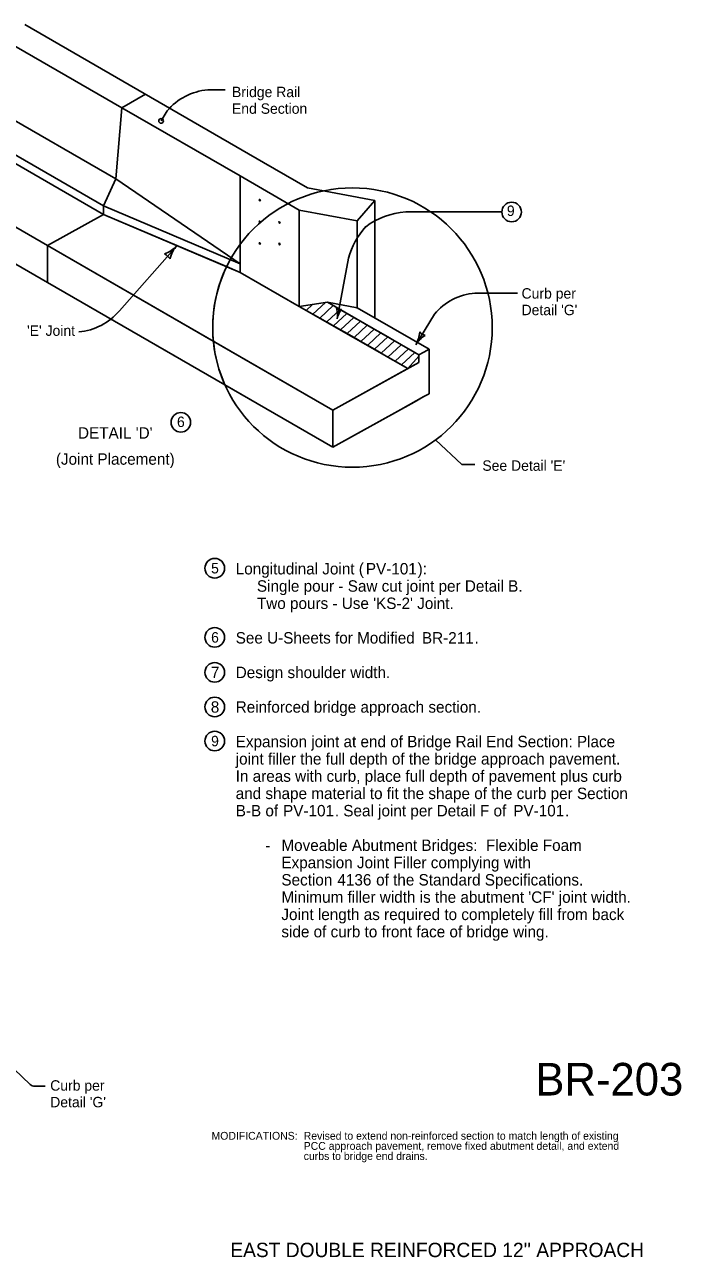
# Model space of a CAD drawing. Extents: x 9234 to 81668, y 5635 to 15999.
# Drawn here: x 19394 to 20400, y 12314 to 14204 of the extents above; entities that cross this region are included whole.
import ezdxf

# ---------------------------------------------------------------- set-up
doc = ezdxf.new("R2010")
doc.units = 0
for name, color, linetype in [('Alignment', 7, 'Continuous'), ('PC_REBAR', 7, 'Continuous'), ('PS_BOLT', 7, 'Continuous'), ('PS_CONST', 7, 'Continuous'), ('PS_DIM', 7, 'Continuous'), ('SheetAddenda', 7, 'Continuous'), ('SurEdgeShoulderUnpaved', 7, 'Continuous')]:
    doc.layers.add(name, color=color, linetype=linetype)

msp = doc.modelspace()

# ---------------------------------------------------------------- linework, layer by layer
at = {"layer": 'PC_REBAR'}
msp.add_circle((19602.7, 14056.8), 3.54, dxfattribs=at)
at = {"layer": 'PS_CONST'}
for centre, radius, start, end in [((19956.7, 13735.5), 42.5, 328.7108, 356.7833), ((20029.3, 13691.4), 42.5, 120.6383, 148.7108), ((20011.5, 13743.9), 16.4, 220.9775, 256.4442)]:
    msp.add_arc(centre, radius, start, end, dxfattribs=at)
at = {"layer": 'PS_DIM'}
for p, q in [((19393.7, 14204.4), (19759.7, 13993.1)), ((19542.8, 14076.9), (19357.8, 14183.7)), ((19674.2, 14104.5), (19701.1, 14104.5)), ((19533.4, 13967.8), (19348.4, 14074.6)), ((19723.8, 13972.4), (19542.8, 14076.9)), ((19602.7, 14056.8), (19612, 14072.1)), ((19514.5, 13926.4), (19329.5, 14033.2)), ((19759.7, 13993.1), (19827, 13954.2)), ((19723.8, 13972.4), (19723.8, 13824.5)), ((19814.4, 13920.1), (19723.8, 13972.4)), ((19827, 13954.2), (19930.2, 13934.9)), ((19930.2, 13934.9), (19930.2, 13754.8)), ((19514.5, 13913.3), (19428.7, 13865.7)), ((19514.5, 13913.3), (19428.7, 13865.7)), ((19703.2, 13833.3), (19514.5, 13913.3)), ((19723.8, 13824.5), (19514.5, 13913.3)), ((19814.4, 13920.1), (19814.4, 13772.2)), ((19814.4, 13920.1), (19903.3, 13903.5)), ((19977.6, 13917.5), (20125.1, 13917.5)), ((19903.3, 13770.3), (19903.3, 13903.5)), ((19428.7, 13865.7), (19428.7, 13809.1)), ((19682.8, 13719), (19428.7, 13865.7)), ((19428.7, 13865.7), (19428.7, 13809.1)), ((19428.7, 13865.7), (19682.8, 13719)), ((19428.7, 13865.7), (19865.9, 13613.3)), ((19627.2, 13866), (19538.8, 13765.7)), ((19889.8, 13846.3), (19872.6, 13753.3)), ((19723.8, 13824.5), (19703.2, 13833.3)), ((19814.4, 13772.2), (19723.8, 13824.5)), ((19814.4, 13772.2), (19723.8, 13824.5)), ((19428.7, 13809.1), (19865.9, 13556.7)), ((19428.7, 13809.1), (19700.6, 13652.1)), ((20083.8, 13792.9), (20149, 13792.9)), ((19857.7, 13778.9), (19814.4, 13772.2)), ((19857.7, 13778.9), (19814.4, 13772.2)), ((19877.6, 13736.6), (19814.4, 13772.2)), ((19814.4, 13772.2), (19814.4, 13772.2)), ((19814.4, 13772.2), (19877.6, 13736.6)), ((19977.3, 13679.1), (19814.4, 13772.2)), ((19980.9, 13677), (19814.4, 13772.2)), ((19814.4, 13772.2), (19814.4, 13772.2)), ((19834.7, 13775.3), (19824.9, 13766.3)), ((19854.9, 13778.4), (19835.5, 13760.4)), ((19866.7, 13773.7), (19846, 13754.5)), ((19877.1, 13767.6), (19856.6, 13748.6)), ((19898, 13755.6), (19857.7, 13778.9)), ((19903.3, 13770.3), (19857.7, 13778.9)), ((19857.7, 13778.9), (19898, 13755.6)), ((19997.8, 13698), (19857.7, 13778.9)), ((19857.7, 13778.9), (19903.3, 13770.3)), ((19887.6, 13761.6), (19867.2, 13742.7)), ((20013.5, 13706.7), (19903.3, 13770.3)), ((20013.5, 13706.7), (19903.3, 13770.3)), ((19993, 13713.5), (20021.6, 13760.5)), ((19877.6, 13736.6), (19898, 13755.6)), ((19898, 13755.6), (19877.6, 13736.6)), ((19898, 13755.6), (19877.6, 13736.6)), ((19888, 13730.6), (19908.4, 13749.6)), ((19908.4, 13749.6), (19888, 13730.6)), ((19908.4, 13749.6), (19888, 13730.6)), ((19908.4, 13749.6), (19898, 13755.6)), ((19898, 13755.6), (19908.4, 13749.6)), ((19898.4, 13724.6), (19918.8, 13743.6)), ((19918.8, 13743.6), (19898.4, 13724.6)), ((19918.8, 13743.6), (19898.4, 13724.6)), ((19918.8, 13743.6), (19908.4, 13749.6)), ((19908.4, 13749.6), (19918.8, 13743.6)), ((19929.2, 13737.6), (19918.8, 13743.6)), ((19918.8, 13743.6), (19929.2, 13737.6)), ((19877.6, 13736.6), (19888, 13730.6)), ((19888, 13730.6), (19898.4, 13724.6)), ((19898.4, 13724.6), (19908.8, 13718.6)), ((19908.8, 13718.6), (19929.2, 13737.6)), ((19929.2, 13737.6), (19908.8, 13718.6)), ((19929.2, 13737.6), (19908.8, 13718.6)), ((19939.5, 13731.6), (19919.4, 13713)), ((19929.6, 13706.6), (19950, 13725.6)), ((19950, 13725.6), (19929.6, 13706.6)), ((19950, 13725.6), (19929.6, 13706.6)), ((19960.4, 13719.6), (19950, 13725.6)), ((19950, 13725.6), (19960.4, 13719.6)), ((19682.8, 13719), (19865.9, 13613.3)), ((19865.9, 13613.3), (19682.8, 13719)), ((19908.8, 13718.6), (19929.6, 13706.6)), ((19929.6, 13706.6), (19940, 13700.6)), ((19940, 13700.6), (19960.4, 13719.6)), ((19960.4, 13719.6), (19940, 13700.6)), ((19960.4, 13719.6), (19940, 13700.6)), ((19970.9, 13713.5), (19950.5, 13694.5)), ((19981.9, 13707.2), (19961.5, 13688.2)), ((20013.5, 13706.7), (20005.6, 13702.3)), ((20005.6, 13702.3), (20013.5, 13706.7)), ((20013.5, 13706.7), (20005.6, 13702.3)), ((20013.5, 13638.4), (20013.5, 13706.7)), ((19865.9, 13613.3), (19997.8, 13686.3)), ((19940, 13700.6), (19950.5, 13694.5)), ((19950.5, 13694.5), (19971.2, 13682.6)), ((19971.2, 13682.6), (19991.6, 13701.5)), ((19991.6, 13701.5), (19971.2, 13682.6)), ((19991.6, 13701.5), (19971.2, 13682.6)), ((19980.9, 13677), (19997.8, 13696.1)), ((19997.8, 13696.1), (19980.9, 13677)), ((19980.9, 13677), (19997.8, 13696.1)), ((19997.8, 13686.3), (19980.9, 13677)), ((19980.9, 13677), (19997.8, 13686.3)), ((19997.8, 13698), (19991.6, 13701.5)), ((19991.6, 13701.5), (19997.8, 13698)), ((20005.6, 13702.3), (19997.8, 13698)), ((19997.8, 13698), (20005.6, 13702.3)), ((20005.6, 13702.3), (19997.8, 13698)), ((19997.8, 13696.1), (19997.8, 13698)), ((19997.8, 13686.3), (19997.8, 13698)), ((19997.8, 13686.3), (19997.8, 13696.1)), ((19865.9, 13613.3), (19980.9, 13677)), ((19980.9, 13677), (19865.9, 13613.3)), ((19971.2, 13682.6), (19977.3, 13679.1)), ((19980.9, 13677), (19977.3, 13679.1)), ((19977.3, 13679.1), (19980.9, 13677)), ((19700.6, 13652.1), (19865.9, 13556.7)), ((19970.4, 13614.5), (20005.6, 13634.1)), ((19990.5, 13625.7), (20005.6, 13634.1)), ((20005.6, 13634.1), (20013.5, 13638.4)), ((20013.5, 13638.4), (20005.6, 13634.1)), ((19865.9, 13556.7), (19990.5, 13625.7)), ((19865.9, 13556.7), (19865.9, 13613.3)), ((20023.4, 13567.7), (20063.8, 13529.7)), ((20063.8, 13529.7), (20083.6, 13529.7)), ((19365.1, 12614.3), (19402.3, 12579.4)), ((19409.1, 12576.7), (19425, 12576.7))]:
    msp.add_line(p, q, dxfattribs=at)
for points in [[(19542.8, 14076.9), (19578.6, 14097.6)], [(19514.5, 13913.3), (19514.5, 13926.4), (19533.4, 13967.8), (19542.8, 14076.9)], [(19514.5, 13913.3), (19329.5, 14020.1)], [(19243.7, 13972.5), (19428.7, 13865.7)], [(19514.5, 13926.4), (19723.8, 13837.6), (19533.4, 13967.8)], [(19903.3, 13903.5), (19930.2, 13934.9)], [(19428.7, 13809.1), (19243.7, 13915.9)], [(19514.5, 13913.3), (19428.7, 13865.7)], [(19428.7, 13809.1), (19428.7, 13865.7)], [(19814.4, 13772.2), (19814.4, 13772.2)], [(19903.3, 13770.3), (19902.5, 13769.9), (19903.3, 13770.3)], [(19898.4, 13724.6), (19888, 13730.6), (19877.6, 13736.6)], [(19929.6, 13706.6), (19908.8, 13718.6), (19898.4, 13724.6)], [(19950, 13725.6), (19939.5, 13731.6), (19929.2, 13737.6)], [(19929.2, 13737.6), (19939.5, 13731.6), (19950, 13725.6)], [(19977.3, 13679.1), (19971.2, 13682.6), (19950.5, 13694.5), (19940, 13700.6), (19929.6, 13706.6)], [(19991.6, 13701.5), (19981.9, 13707.2), (19960.4, 13719.6)], [(19960.4, 13719.6), (19981.9, 13707.2), (19991.6, 13701.5)], [(20013.5, 13706.7), (20013.5, 13638.4)], [(19997.8, 13698), (19997.8, 13696.1), (19997.8, 13686.3)], [(19865.9, 13556.7), (19970.4, 13614.5), (19990.5, 13625.7)]]:
    msp.add_lwpolyline(points, dxfattribs=at)
for centre, radius in [((19896, 13739.9), 214.2), ((20140, 13917.1), 15), ((19633, 13594.6), 15), ((19685, 13370.9), 15), ((19685, 13264.9), 15), ((19685, 13211.2), 15), ((19685, 13158.2), 15), ((19685, 13105.9), 15)]:
    msp.add_circle(centre, radius, dxfattribs=at)
for centre, radius, start, end in [((19681.9, 14013.7), 91, 94.8409, 140.1467), ((19986.5, 13800.3), 117.5, 94.3399, 126.627), ((20003.2, 13815.4), 117.5, 137.5971, 164.7195), ((19591, 13898.1), 48.4, 290.4433, 318.5158), ((19663.5, 13834), 48.4, 138.5158, 166.5883), ((19600.4, 13835.6), 18.7, 30.7825, 66.2492), ((19896, 13739.9), 214.2, 154.1687, 185.6063), ((19896, 13739.9), 214.2, 154.1687, 185.6063), ((20091.5, 13702.2), 91, 94.8409, 140.1467), ((19468.9, 13824), 91, 274.8409, 320.1467), ((19877.5, 13779.9), 12.5, 241.782, 277.2487), ((19840.9, 13759.2), 32.3, 349.5153, 17.5878), ((19904.3, 13747.5), 32.3, 141.4428, 169.5153), ((19896, 13739.9), 214.2, 185.6063, 204.2018), ((19896, 13739.9), 214.2, 185.6063, 204.2018), ((19409.1, 12586.7), 10, 226.7172, 270)]:
    msp.add_arc(centre, radius, start, end, dxfattribs=at)
for centre in [(19754, 13935.3), (19754, 13902.1), (19784.2, 13901.2), (19754, 13868.9), (19784.2, 13868)]:
    msp.add_ellipse(centre, major_axis=(0.67, -1.15), ratio=0.57735, dxfattribs=at)

# ---------------------------------------------------------------- texts
at = {"layer": 'Alignment'}
msp.add_text('MODIFICATIONS:', height=12, dxfattribs=at).set_placement((19680, 12494.6))
at = {"layer": 'PS_BOLT'}
for s, height, p in [('6', 16, (19627.1, 13587.4)), ('(Joint Placement)', 17.5, (19441.5, 13529.6))]:
    msp.add_text(s, height=height, dxfattribs=at).set_placement(p)
at = {"layer": 'PS_DIM'}
for s, height, p in [('Bridge Rail ', 16, (19711.4, 14093.2)), ('End Section', 16, (19711.4, 14067.7)), ('Curb per', 16, (20155.2, 13784.3)), ("Detail 'G'", 16, (20155.2, 13758.9)), ("'E' Joint", 16, (19397.3, 13727.2)), ("DETAIL 'D'", 17.5, (19475.4, 13569.6)), ("See Detail 'E'", 16, (20095.1, 13520.3)), ('Curb per', 16, (19432.8, 12569.8)), ("Detail 'G'", 16, (19432.8, 12544.3))]:
    msp.add_text(s, height=height, dxfattribs=at).set_placement(p)
at = {"layer": 'SheetAddenda'}
for s, height, p in [('9', 16, (20132.7, 13911)), ('5', 16, (19679.4, 13362.9)), ('Longitudinal Joint (', 17.5, (19717.1, 13361.4)), ('PV-101', 17.5, (19916.6, 13361.4)), ('):', 17.5, (19995.9, 13361.4)), ('     Single pour - Saw cut joint per Detail B.', 17.5, (19717.1, 13334.9)), ("     Two pours - Use 'KS-2' Joint.", 17.5, (19717.1, 13308.4)), ('6', 16, (19679.4, 13256.9)), ('See U-Sheets for Modified ', 17.5, (19717.1, 13255.4)), ('BR-211', 17.5, (20002.5, 13255.4)), ('.', 17.5, (20083.1, 13255.4)), ('7', 17.5, (19679.1, 13202.4)), ('Design shoulder width.', 17.5, (19717.1, 13202.4)), ('8', 17.5, (19678.9, 13149.4)), ('Reinforced bridge approach section.', 17.5, (19717.1, 13149.4)), ('9', 16, (19679.4, 13097.9)), ('Expansion joint at end of Bridge Rail End Section: Place', 17.5, (19717.1, 13096.4)), ('joint filler the full depth of the bridge approach pavement.', 17.5, (19717.1, 13069.9)), ('In areas with curb, place full depth of pavement plus curb', 17.5, (19717.1, 13043.4)), ('and shape material to fit the shape of the curb per Section', 17.5, (19717.1, 13016.9)), ('B-B of ', 17.5, (19717.1, 12990.4)), ('PV-101', 17.5, (19789.7, 12990.4)), ('. Seal joint per Detail F of ', 17.5, (19869, 12990.4)), ('PV-101', 17.5, (20142.5, 12990.4)), ('.', 17.5, (20221.8, 12990.4)), ('Moveable Abutment Bridges:  Flexible Foam', 17.5, (19787.1, 12937.4)), ('       -', 17.5, (19717.1, 12937.4)), ('Expansion Joint Filler complying with ', 17.5, (19787.1, 12910.9)), ('Section ', 17.5, (19787.1, 12884.4)), ('4136', 17.5, (19873, 12884.4)), (' of the Standard Specifications.', 17.5, (19925.8, 12884.4)), ("Minimum filler width is the abutment 'CF' joint width.", 17.5, (19787.1, 12857.9)), ('Joint length as required to completely fill from back ', 17.5, (19787.1, 12831.4)), ('side of curb to front face of bridge wing.', 17.5, (19787.1, 12804.9))]:
    msp.add_text(s, height=height, dxfattribs=at).set_placement(p)
at = {"layer": 'SurEdgeShoulderUnpaved'}
for s, height, p in [('BR-203', 50, (20176.3, 12562.4)), ('Revised to extend non-reinforced section to match length of existing ', 12, (19821.3, 12494.6)), ('curbs to bridge end drains.', 12, (19821.3, 12463.6)), ('PCC approach pavement, remove fixed abutment detail, and extend ', 12, (19821.3, 12479.1)), ("EAST DOUBLE REINFORCED 12'' APPROACH", 22, (19708.8, 12314.6))]:
    msp.add_text(s, height=height, dxfattribs=at).set_placement(p)

doc.saveas('drawing.dxf')
